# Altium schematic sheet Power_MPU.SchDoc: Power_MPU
size A3; CompanyName: STMicroelectronics; SheetNumber: 4; SheetTotal: 7
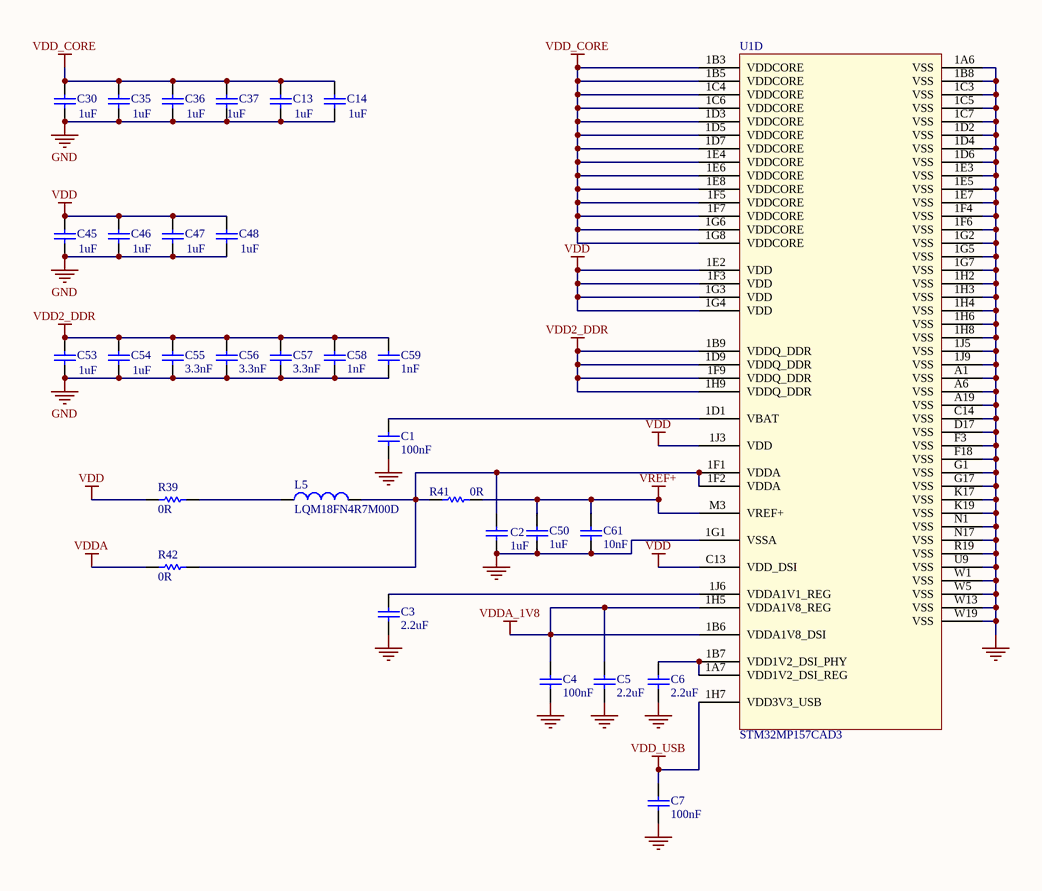
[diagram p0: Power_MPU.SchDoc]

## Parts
C1  value 100nF  [C0402]
C2  value 1uF  [C0402]
C3  value 2.2uF  [C0402]
C4  value 100nF  [C0402]
C5  value 2.2uF  [C0402]
C6  value 2.2uF  [C0402]
C7  value 100nF  [C0402]
C13  value 1uF  [C0402]
C14  value 1uF  [C0402]
C30  value 1uF  [C0402]
C35  value 1uF  [C0402]
C36  value 1uF  [C0402]
C37  value 1uF  [C0402]
C45  value 1uF  [C0402]
C46  value 1uF  [C0402]
C47  value 1uF  [C0402]
C48  value 1uF  [C0402]
C50  value 1uF  [C0402]
C53  value 1uF  [C0402]
C54  value 1uF  [C0402]
C55  value 3.3nF  [C0402]
C56  value 3.3nF  [C0402]
C57  value 3.3nF  [C0402]
C58  value 1nF  [C0402]
C59  value 1nF  [C0402]
C61  value 10nF  [C0402]
L5  value LQM18FN4R7M00D  [L0603_H0P8]
R39  value 0R  [R0402]
R41  value 0R  [R0402]
R42  value 0R  [R0402]
U1  value STM32MP157CAD3  [ICC_TFBGA257_10X10_STM32MP157CAD3_P050-065]  (part D of 5)

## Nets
GND: C1.1 C2.1 C3.1 C4.1 C5.1 C6.1 C7.1 C13.1 C14.1 C30.1 C35.1 C36.1 C37.1 C45.1 C46.1 C47.1 C48.1 C50.1 C53.1 C54.1 C55.1 C56.1 C57.1 C58.1 C59.1 C61.1 U1.1A6(VSS) U1.1B8(VSS) U1.1C3(VSS) U1.1C5(VSS) U1.1C7(VSS) U1.1D2(VSS) U1.1D4(VSS) U1.1D6(VSS) U1.1E3(VSS) U1.1E5(VSS) U1.1E7(VSS) U1.1F4(VSS) U1.1F6(VSS) U1.1G1(VSSA) U1.1G2(VSS) U1.1G5(VSS) U1.1G7(VSS) U1.1H2(VSS) U1.1H3(VSS) U1.1H4(VSS) U1.1H6(VSS) U1.1H8(VSS) U1.1J5(VSS) U1.1J9(VSS) U1.A1(VSS) U1.A6(VSS) U1.A19(VSS) U1.C14(VSS) U1.D17(VSS) U1.F3(VSS) U1.F18(VSS) U1.G1(VSS) U1.G17(VSS) U1.K17(VSS) U1.K19(VSS) U1.N1(VSS) U1.N17(VSS) U1.R19(VSS) U1.U9(VSS) U1.W1(VSS) U1.W5(VSS) U1.W13(VSS) U1.W19(VSS)
VDD: C45.2 C46.2 C47.2 C48.2 R39.1 U1.1E2(VDD) U1.1F3(VDD) U1.1G3(VDD) U1.1G4(VDD) U1.1J3(VDD) U1.C13(VDD_DSI)
VDD2_DDR: C53.2 C54.2 C55.2 C56.2 C57.2 C58.2 C59.2 U1.1B9(VDDQ_DDR) U1.1D9(VDDQ_DDR) U1.1F9(VDDQ_DDR) U1.1H9(VDDQ_DDR)
VDD_CORE: C13.2 C14.2 C30.2 C35.2 C36.2 C37.2 U1.1B3(VDDCORE) U1.1B5(VDDCORE) U1.1C4(VDDCORE) U1.1C6(VDDCORE) U1.1D3(VDDCORE) U1.1D5(VDDCORE) U1.1D7(VDDCORE) U1.1E4(VDDCORE) U1.1E6(VDDCORE) U1.1E8(VDDCORE) U1.1F5(VDDCORE) U1.1F7(VDDCORE) U1.1G6(VDDCORE) U1.1G8(VDDCORE)
VDD_USB: C7.2 U1.1H7(VDD3V3_USB)
VDDA: R42.1
VDDA_1V8: C4.2 C5.2 U1.1B6(VDDA1V8_DSI) U1.1H5(VDDA1V8_REG)
VREF+: C50.2 C61.2 R41.2 U1.M3(VREF+)
NetC1_2: C1.2 U1.1D1(VBAT)
NetC2_2: C2.2 L5.2 R41.1 R42.2 U1.1F1(VDDA) U1.1F2(VDDA)
NetC3_2: C3.2 U1.1J6(VDDA1V1_REG)
NetC6_2: C6.2 U1.1A7(VDD1V2_DSI_REG) U1.1B7(VDD1V2_DSI_PHY)
NetL5_1: L5.1 R39.2

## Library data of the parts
C1 C4 C7 = MCD-00006: Capacitor, MLCC, 100nF, 16V, X7R, 10%, 0402, T=0.5mm; Manufacturer_Part_Number: CC0402KRX7R7BB104; Manufacturer: YAGEO; Alternate_Manufacturer_Part_Number: GCM155R71C104KA55D; Alternate_Manufacturer: MURATA; ECCN_US: EAR99; ECCN_EU: NEC; Provided_By: SUBCO
C2 C13 C14 C30 C35-C37 C45-C48 C50 C53 C54 = MCD-00095: Capacitor, MLCC, 1uF, 25V, X5R, 10%, 0402, T=0,5mm; Manufacturer_Part_Number: GRM155R61E105KA12; Manufacturer: MURATA; Alternate_Manufacturer_Part_Number: GRM155R60J105KE19; ECCN_US: EAR99; ECCN_EU: NEC; Provided_By: SUBCO
C3 C5 C6 = MCD-01823: Capacitor,MLCC,2.2uF,6V3,X5R,10%,0402,T=0.5; Manufacturer_Part_Number: GRM155R60J225KE95D; Manufacturer: MURATA; ECCN_US: EAR99; ECCN_EU: NEC; Provided_By: SUBCO
C55-C57 = MCD-01462: Capacitor, MLCC, 3.3nF, 16V, X7R, 10%, 0402, T=0.5mm; Manufacturer_Part_Number: CC0402KRX7R7BB332; Manufacturer: YAGEO; Provided_By: SUBCO
C58 C59 = MCD-00198: Capacitor, MLCC, 1nF, 16V, X7R, 10%, 0402, T=0.5mm; Manufacturer_Part_Number: CC0402KRX7R7BB102; Manufacturer: YAGEO; Provided_By: SUBCO; ECCN_US: EAR99; ECCN_EU: NEC
C61 = MCD-00011: Capacitor, MLCC, 10nF, 16V, X7R, 10%, 0402, T=0.5mm; Manufacturer_Part_Number: CC0402KRX7R7BB103; Manufacturer: YAGEO; ECCN_US: EAR99; ECCN_EU: NEC; Provided_By: SUBCO
L5 = MCD-01134: IND 4.7uH 20% 80mA 600mhom 0603; Part_Type: Inductor; Manufacturer: MURATA; Provided_By: SUBCO
R39 R42 = MCD-00052: Resistor,0R,0402,5%,1/16W; Manufacturer_Part_Number: RC0402JR-070RL; Manufacturer: YAGEO; Provided_By: SUBCO; ECCN_US: EAR99; ECCN_EU: NEC
R41 = MCD-00052: Resistor,0R,0402,5%,1/16W; Manufacturer_Part_Number: RC0402JR-070RL; Manufacturer: YAGEO; ECCN_US: EAR99; ECCN_EU: NEC; Provided_By: SUBCO
U1 = MCD-01144: MPU TFBGA10x10 secure boot+crypto; Part_Type: IC; Manufacturer: STMICROELECTRONICS; Provided_By: SUBCO with ST control; ECCN_US: 5A002A4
